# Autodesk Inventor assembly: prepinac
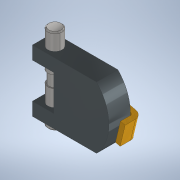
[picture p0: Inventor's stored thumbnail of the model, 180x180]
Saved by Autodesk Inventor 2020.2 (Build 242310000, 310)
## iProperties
Created: 2020-04
Part Number: prepinac
Document SubType Name: Assembly
Designer: freem
Author: freem
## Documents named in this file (6)
- C:\Users\freem\Projects\school\Kratochvil\prepinac\prepinac.iam
- C:\Users\freem\Projects\school\Kratochvil\prepinac\deska.ipt
- C:\Users\freem\Projects\school\Kratochvil\prepinac\tahlo.ipt
- C:\Users\freem\Projects\school\Kratochvil\prepinac\nyt.ipt
- C:\Users\freem\Projects\school\Kratochvil\prepinac\packa.ipt
- C:\Users\freem\Projects\school\Kratochvil\prepinac\sroub_m5.ipt
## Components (5 placed, 5 different names)
1. deska:1 — Mate:1, Mate:2, Mate:3, Mate:8, Mate:9, Mate:10, Flush:1
2. tahlo:1 — Mate:1, Tangent:1, Flush:1
3. nyt:1 — Mate:4, Mate:5, Tangent:1
4. packa:1 — Mate:2, Mate:3, Mate:4, Mate:5, Mate:6, Mate:7
5. sroub_m5:1 — Mate:6, Mate:7, Angle:1
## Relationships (13: Mate 10, Tangent 1, Angle 1, Flush 1)
- Mate:1: deska:1 ↔ tahlo:1
- Mate:2: deska:1 ↔ packa:1
- Mate:3: deska:1 ↔ packa:1
- Mate:4: nyt:1 ↔ packa:1
- Mate:5: nyt:1 ↔ packa:1
- Tangent:1: tahlo:1 ↔ nyt:1
- Mate:6: packa:1 ↔ sroub_m5:1
- Mate:7: packa:1 ↔ sroub_m5:1
- Mate:8: deska:1
- Mate:9: deska:1
- Mate:10: deska:1
- Angle:1: sroub_m5:1
- Flush:1: deska:1 ↔ tahlo:1
